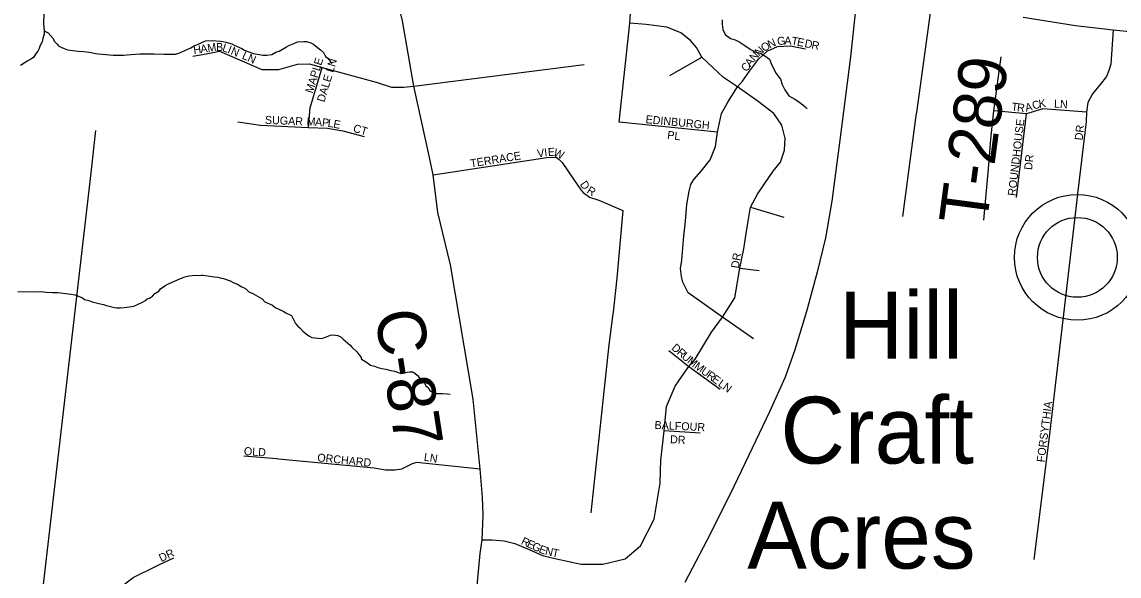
# Model space of a CAD drawing. Extents: x 1310247 to 1664935, y 235267 to 584339.
# Drawn here: x 1455233 to 1462084, y 396572 to 400032 of the extents above; entities that cross this region are included whole.
import ezdxf

# ---------------------------------------------------------------- set-up
doc = ezdxf.new("R2010")
doc.units = 0
for name, color, linetype in [('GM_X_County_Road', 7, 'Continuous'), ('GM_X_County_Road_Text', 7, 'Continuous'), ('GM_X_Interstate_Route', 7, 'Continuous'), ('GM_X_Minor_River', 7, 'Continuous'), ('GM_X_Township_Road', 7, 'Continuous'), ('GM_X_Township_Road_Text', 7, 'Continuous'), ('GM_X_Township_Subdivision', 7, 'Continuous'), ('GM_X_Township_Subdivision_Text', 7, 'Continuous'), ('GM_X_Unincorporated', 7, 'Continuous'), ('GM_X_Unincorporated_Location', 7, 'Continuous'), ('GM_X_Unincorporated_Text', 7, 'Continuous')]:
    doc.layers.add(name, color=color, linetype=linetype)

msp = doc.modelspace()

# ---------------------------------------------------------------- linework, layer by layer
at = {"layer": 'GM_X_County_Road'}
for points in [[(1457856.3, 395425.4), (1457891.7, 395481), (1457954.8, 395574.4), (1457982.6, 395694.4), (1458009.1, 395866), (1458042.1, 396205.5), (1458050.3, 396268.2), (1458060.8, 396355.2), (1458094.8, 396712.8), (1458106.3, 396798.8), (1458113.2, 396952.5), (1458109.1, 397063.7), (1458095.3, 397239.4), (1458051.4, 397675.8), (1457908.7, 398515.8), (1457829.8, 398842.2), (1457800.3, 399077.4), (1457776.8, 399195.4), (1457679.8, 399630.7), (1457608.8, 400039.4), (1457598.6, 400082.1), (1457587, 400144.7), (1457490, 400571.5)], [(1461485.4, 400062.7), (1461812.9, 400010.4), (1462048.4, 399981.8), (1462170.8, 399970.6)]]:
    msp.add_lwpolyline(points, dxfattribs=at)
at = {"layer": 'GM_X_Interstate_Route'}
msp.add_lwpolyline([(1460449.2, 400206.5), (1460406.1, 399814.6), (1460343.4, 399311), (1460290.1, 398913.5), (1460250.5, 398684.1), (1460199.2, 398469.2), (1460133, 398224.6), (1460059, 397984.3), (1459999.2, 397813.7), (1459901.9, 397596.3), (1459772.7, 397325.7), (1459656.5, 397082.8), (1459510.6, 396792.8), (1459371.8, 396532.6)], dxfattribs=at)
at = {"layer": 'GM_X_Minor_River'}
for points in [[(1455219, 400237.4), (1455264.8, 400214.5), (1455296.6, 400197.9), (1455316.6, 400189.5), (1455348.3, 400166.8), (1455356, 400148.6), (1455365.5, 400118.3), (1455369.2, 400094.2), (1455368.6, 400064.1), (1455366.2, 400038), (1455367.9, 400019.9), (1455369.5, 399997.8), (1455371.2, 399977.7), (1455370.9, 399957.6), (1455362.3, 399927.6), (1455358, 399907.6), (1455343.5, 399879.8), (1455339.2, 399865.8), (1455330.9, 399849.9), (1455316.5, 399830.1)], [(1459605.6, 400045.8), (1459604.9, 400017.8), (1459610.1, 399985.5), (1459625.2, 399953), (1459658.6, 399928), (1459686.4, 399919.3), (1459716.1, 399906.5), (1459747.6, 399885.6), (1459781, 399862.6), (1459810.6, 399845.8), (1459844.4, 399836.9), (1459871.9, 399820.1), (1459901.4, 399799.2), (1459910.7, 399772.9), (1459925.9, 399740.4), (1459943.1, 399709.8), (1459970.2, 399675)], [(1455371.2, 399976.7), (1455397.1, 399963.2), (1455426.6, 399928.5), (1455434.3, 399912.3), (1455452.1, 399894), (1455463.9, 399879.7), (1455495.8, 399867.1), (1455517.7, 399858.7), (1455583.8, 399849.5), (1455617.9, 399846.9), (1455635.9, 399844.5), (1455664, 399842), (1455692, 399835.5), (1455710, 399833.2), (1455780.2, 399826), (1455802.2, 399823.6), (1455866.4, 399824.4), (1455888.5, 399826.1), (1455969, 399832.7), (1456021.2, 399833.8), (1456057.3, 399833.1), (1456121.5, 399830), (1456137.5, 399829.7), (1456191.7, 399830.8), (1456211.9, 399836.5), (1456286.7, 399869.3), (1456309, 399882.9), (1456347.5, 399900.3), (1456363.7, 399908.1), (1456379.8, 399913.8), (1456420, 399917.1), (1456472.1, 399912.2), (1456488.1, 399909.9), (1456506.1, 399905.6), (1456544.1, 399894.9), (1456558, 399886.6), (1456605.8, 399865.7), (1456621.7, 399855.4), (1456675.6, 399834.3), (1456701.6, 399829.9), (1456739.6, 399825.2), (1456761.7, 399824.8), (1456793.9, 399828.2), (1456818.2, 399843.9), (1456838.4, 399849.6), (1456885, 399876.8), (1456899.2, 399884.6), (1456929.6, 399898.1), (1456953.8, 399907.8), (1456994, 399909.1), (1457010, 399908.8), (1457036, 399902.3), (1457053.9, 399894), (1457067.7, 399879.7), (1457097.5, 399857), (1457115.3, 399840.7), (1457128.9, 399816.3), (1457142.8, 399806), (1457168.3, 399771.5)], [(1455316.5, 399830.1), (1455304.2, 399810.2), (1455287.9, 399800.5), (1455269.7, 399788.7), (1455223, 399759.4)], [(1459970.2, 399675), (1459981.4, 399640.6), (1459996.5, 399608.1), (1460021.6, 399571.3), (1460059.1, 399550.2), (1460088.6, 399531.4), (1460121.9, 399504.4), (1460137.5, 399490)], [(1456151.6, 398397.9), (1456218.3, 398428.8), (1456250.6, 398440.3), (1456274.8, 398445.9), (1456317, 398451.2), (1456333.1, 398448.9), (1456351.2, 398450.6), (1456365.2, 398450.4), (1456379.2, 398448.1), (1456433.3, 398441.1), (1456455.3, 398438.7), (1456471.3, 398434.4), (1456491.3, 398430.1), (1456533.2, 398415.3), (1456555.1, 398402.8), (1456579, 398394.4), (1456600.9, 398380), (1456628.8, 398367.4), (1456648.5, 398347), (1456674.4, 398336.5), (1456732.1, 398303.4), (1456749.8, 398285), (1456797.7, 398264.1), (1456813.5, 398249.7), (1456863.3, 398226.8), (1456881.2, 398216.4), (1456915, 398197.8), (1456932.5, 398165.3), (1456940.3, 398149.1), (1456956, 398132.8), (1456969.9, 398120.5), (1456987.6, 398100.1), (1457007.4, 398083.7), (1457023.3, 398071.4), (1457043.2, 398061), (1457103.3, 398055.9), (1457117.4, 398059.7), (1457159.8, 398075), (1457175.9, 398078.7), (1457206, 398074.2), (1457225.9, 398063.8), (1457239.7, 398051.5), (1457283.3, 398014.6), (1457295, 397998.3), (1457324.7, 397971.7), (1457336.5, 397955.5), (1457348.3, 397941.2), (1457354, 397927), (1457389.8, 397902.3), (1457409.6, 397887.9), (1457433.6, 397881.5), (1457455.5, 397875.1), (1457479.5, 397868.6), (1457505.5, 397864.1), (1457535.5, 397855.6), (1457559.5, 397851.1), (1457587.5, 397840.6), (1457607.5, 397838.3), (1457637.7, 397845.8), (1457655.8, 397847.5), (1457673.9, 397847.1), (1457687.7, 397836.8), (1457701.6, 397826.6), (1457715.4, 397810.3), (1457737.1, 397789.8), (1457748.9, 397773.5), (1457754.7, 397759.4), (1457768.6, 397749.1), (1457780.3, 397730.8), (1457806.1, 397714.3), (1457822.1, 397712), (1457858.3, 397711.4), (1457888.3, 397708.8), (1457906.4, 397708.5)], [(1455207.3, 398348.2), (1455313.6, 398346.3), (1455351.8, 398347.7), (1455367.8, 398347.4), (1455383.9, 398345.1), (1455424, 398342.4), (1455440, 398342.1), (1455456.1, 398341.8), (1455522.2, 398334.6), (1455540.2, 398332.3), (1455562.2, 398327.9), (1455596.1, 398315.3), (1455610.1, 398309), (1455624, 398298.7), (1455650, 398292.2), (1455671.9, 398283.8), (1455711.9, 398273.1), (1455741.9, 398268.5), (1455759.8, 398262.2), (1455809.8, 398249.3), (1455823.8, 398247), (1455847.9, 398246.6), (1455870, 398248.2), (1455888.1, 398249.9), (1455930.4, 398257.2), (1455985, 398282.3), (1455999.2, 398290.1), (1456015.4, 398301.9), (1456029.6, 398307.7), (1456047.9, 398319.4), (1456062.2, 398335.2), (1456086.5, 398350.8), (1456098.8, 398364.7), (1456131.3, 398388.2), (1456151.6, 398397.9)]]:
    msp.add_lwpolyline(points, dxfattribs=at)
at = {"layer": 'GM_X_Township_Road'}
for points in [[(1460819.9, 399462.9), (1460820.4, 399466.4), (1460915, 400149.1)], [(1460735, 398816.4), (1460819.9, 399462.9)]]:
    msp.add_lwpolyline(points, dxfattribs=at)
at = {"layer": 'GM_X_Township_Subdivision'}
for points in [[(1459575.7, 399343), (1458962.1, 399405.5), (1459029.4, 400024.5), (1459051.7, 400376.9)], [(1459997.9, 399312.6), (1459978.5, 399387.6), (1459928.8, 399460.3), (1459830.6, 399534.2), (1459701.9, 399626), (1459614.8, 399684.2), (1459551.9, 399743.1), (1459477.7, 399811.1), (1459446.3, 399872), (1459408.7, 399915.7), (1459347.7, 399963.4), (1459259.4, 399999), (1459130.3, 400015), (1459029.4, 400024.5)], [(1462048.4, 399981.8), (1462032.4, 399768.9), (1462020.6, 399728.6), (1462006.8, 399691.1), (1461966.6, 399640.6), (1461919.5, 399583.4), (1461889.4, 399528.6), (1461881.9, 399468.7), (1461878.7, 399410.9), (1461825.6, 398959.3), (1461825.3, 398956.8)], [(1459801.7, 398053.1), (1459608.1, 398189.3), (1459392.8, 398340.8), (1459374.4, 398377.6), (1459359.5, 398406.7), (1459352.6, 398441.6), (1459346.2, 398491.3), (1459353.8, 398543.6), (1459366.6, 398694), (1459376.8, 398788.4), (1459385.7, 398892.9), (1459399.7, 398975.8), (1459409.9, 399017.9), (1459427.8, 399048.4), (1459473.7, 399099.5), (1459529.8, 399170.9), (1459564.2, 399255), (1459575.7, 399343), (1459601.2, 399460.3), (1459640.7, 399531.6), (1459701.9, 399626), (1459731.6, 399662.8), (1459776.3, 399724.8), (1459833.1, 399799.9), (1459886, 399848.7), (1459951, 399878.1), (1460032.2, 399882.2), (1460125.6, 399863.9)], [(1456300.4, 399818.5), (1456383.3, 399833.8), (1456466.2, 399849.1), (1456731.4, 399734.5), (1456837.2, 399734.5), (1456954, 399768.3), (1457028.2, 399770.5), (1457106.7, 399746.5), (1457445.5, 399656.5), (1457540.4, 399625.2), (1457616.8, 399624.9), (1457679.4, 399630.7)], [(1459279.8, 399698.5), (1459477.7, 399811.1)], [(1461238.8, 398793.2), (1461270, 399114.8), (1461282.9, 399300.4), (1461301.3, 399476.8), (1461347.2, 399815)], [(1457021.2, 399372.3), (1457032.1, 399495.7), (1457106.7, 399746.5)], [(1457679.4, 399630.7), (1457679.8, 399630.7), (1458744, 399766.4)], [(1461881.9, 399468.7), (1461608.4, 399490.2), (1461507.1, 399458.5), (1461301.3, 399476.8)], [(1456580.9, 399408), (1456722.4, 399387.8), (1457021.2, 399372.3), (1457141.3, 399369.1), (1457237.6, 399351.8), (1457370.7, 399317.1)], [(1461444.6, 398934.7), (1461507.1, 399458.5)], [(1455664.1, 399089.2), (1455694.6, 399353.7)], [(1459220.6, 397231.5), (1459223.1, 397293.5), (1459242.9, 397477.7), (1459258.2, 397630.7), (1459311.7, 397758.2), (1459357.6, 397824.5), (1459397.6, 397880.9), (1459436.7, 397926.5), (1459538.7, 398094.8), (1459608.1, 398189.3), (1459684, 398309), (1459716.2, 398493.6), (1459740.1, 398615), (1459752.9, 398699.1), (1459768.2, 398788.4), (1459783.5, 398875.1), (1459826.8, 398956.6), (1459870.2, 399020.4), (1459923.7, 399100.7), (1459969.6, 399155.6), (1459995.1, 399232), (1459999, 399308.6), (1459997.9, 399312.6)], [(1457800.3, 399077.4), (1458511.6, 399185.2), (1458569.6, 399188.3), (1458588, 399173.4), (1458607.2, 399153.8), (1458676.2, 399050.7), (1458722.1, 398984.6), (1458736.6, 398967.4), (1458776.1, 398938.5), (1458836, 398919.1), (1458985.4, 398853.5), (1458947.4, 398431.4), (1458925.1, 398220.3), (1458923.5, 398208.4)], [(1455235.8, 395385.9), (1455664.1, 399089.2), (1455664.1, 399089.2)], [(1461825.3, 398956.8), (1461644.8, 397421.9), (1461551.1, 396675.7)], [(1459783.5, 398875.1), (1459990, 398813.9)], [(1459716.2, 398493.6), (1459837.6, 398480.8)], [(1458923.5, 398208.4), (1458897.6, 398015.7), (1458785.7, 396966.3)], [(1459273.5, 397980), (1459397.6, 397880.9), (1459593.1, 397738.6)], [(1459467.3, 397465), (1459242.9, 397477.7)], [(1456823.8, 397303), (1456618.6, 397320.5)], [(1458095.3, 397239.4), (1457697.4, 397281.7), (1457669.3, 397273.4), (1457640.7, 397259), (1457602.8, 397239.6), (1457563.8, 397233.5), (1457503.4, 397233.5), (1457431.7, 397244.7), (1456834.7, 397302.1), (1456823.8, 397303)], [(1458106.3, 396798.8), (1458169.5, 396798.8), (1458243.6, 396792), (1458310.8, 396774.1), (1458400, 396737), (1458483.8, 396700), (1458570.2, 396679.4), (1458725.6, 396646.5), (1458859.9, 396646.5), (1458999.9, 396678.7), (1459096.2, 396761.2), (1459181.5, 396926.5), (1459217.4, 397151.6), (1459220.6, 397231.5)], [(1456090.9, 396643.2), (1456181.9, 396686.6)], [(1455695.6, 395280.5), (1455823.1, 396431.8), (1455875.3, 396524.2), (1455926.9, 396561.9), (1456062.5, 396629.6), (1456090.9, 396643.2)]]:
    msp.add_lwpolyline(points, dxfattribs=at)
at = {"layer": 'GM_X_Unincorporated'}
for radius in [392.8, 249]:
    msp.add_circle((1461823.9, 398561.9), radius, dxfattribs=at)
at = {"layer": 'GM_X_Unincorporated_Location'}
msp.add_line((1461823.9, 398561.9), (1461823.9, 398561.9), dxfattribs=at)

# ---------------------------------------------------------------- texts
at = {"layer": 'GM_X_County_Road_Text'}
msp.add_text('C-87', height=300, rotation=278.88173, dxfattribs=at).set_placement((1457435.3, 398216.9))
at = {"layer": 'GM_X_Township_Road_Text'}
msp.add_text('T-289', height=300, rotation=82.466, dxfattribs=at).set_placement((1461256.1, 398754.6))
at = {"layer": 'GM_X_Township_Subdivision_Text'}
for s, rotation, p in [('A', 359.82512, (1459993.7, 399891)), ('H', 8.11464, (1456306.8, 399831.3)), ('A', 8.093, (1456350.4, 399837.5)), ('M', 8.12067, (1456394, 399843.7)), ('B', 358.5673, (1456444.1, 399851)), ('L', 341.94518, (1456479.9, 399850.6)), ('I', 337.85765, (1456512.5, 399840.1)), ('N', 337.8374, (1456532.8, 399831.8)), ('N', 42.20164, (1459836.3, 399814.9)), ('O', 32.74441, (1459867.2, 399843.1)), ('N', 23.34781, (1459902.3, 399865.9)), ('G', 5.97811, (1459951.4, 399886.5)), ('T', 350.44784, (1460035.6, 399891.1)), ('E', 348.33646, (1460069.8, 399885.3)), ('D', 348.22267, (1460117.2, 399875.5)), ('R', 348.23602, (1460160.3, 399866.5)), ('LN', 336.02625, (1456602.8, 399804.2)), ('MAPLE', 72.7179, (1457047.9, 399583)), ('N', 48.41727, (1459808.1, 399783)), ('DALE LN', 73.39085, (1457121.3, 399527.5)), ('C', 53.9994, (1459758.9, 399717)), ('A', 52.57932, (1459782, 399748.8)), ('C', 18.81326, (1461551.2, 399482.9)), ('K', 8.35571, (1461586.3, 399495.1)), ('LN', 356.97755, (1461677.2, 399497.2)), ('T', 352.65811, (1461409.6, 399479.5)), ('R', 352.73134, (1461444.6, 399475)), ('A', 13.6054, (1461503.6, 399471.1)), ('SUGAR', 357.56454, (1456749.1, 399396)), ('M', 356.11809, (1457008.9, 399387.2)), ('A', 356.12776, (1457061.6, 399383.6)), ('P', 355.07524, (1457105.2, 399380.7)), ('L', 351.16659, (1457139.4, 399377.8)), ('E', 349.64384, (1457173.8, 399372.4)), ('EDINBURGH', 354.42825, (1459125.6, 399400.4)), ('ROUNDHOUSE', 83.46221, (1461438.5, 398943.3)), ('CT', 343.60907, (1457296.9, 399347.3)), ('PL', 352.87835, (1459260.5, 399302.7)), ('DR', 83.99458, (1461856.5, 399290.8)), ('TERRACE', 9.16423, (1458036.4, 399123.1)), ('V', 8.31246, (1458454.3, 399184.7)), ('I', 7.05454, (1458497.6, 399191)), ('E', 4.18292, (1458518.8, 399193.7)), ('W', 337.95821, (1458547.9, 399197.2)), ('DR', 83.99458, (1461540.7, 399105.9)), ('D', 305.52752, (1458714.7, 399017.5)), ('R', 327.99316, (1458755.5, 398967.4)), ('DR', 81.03268, (1459709.4, 398490.5)), ('D', 319.62631, (1459284.8, 397990.2)), ('R', 319.60679, (1459318.3, 397961.7)), ('U', 319.61703, (1459348.4, 397936)), ('M', 321.67582, (1459383.5, 397906.3)), ('M', 323.74529, (1459426.4, 397872.3)), ('U', 323.78865, (1459469, 397841.1)), ('R', 323.79781, (1459504.5, 397815.1)), ('E', 323.78582, (1459536.5, 397791.7)), ('L', 323.78582, (1459575.6, 397763.1)), ('N', 323.80443, (1459604, 397742.3)), ('FORSYTHIA', 82.78307, (1461618.9, 397280.2)), ('BALFOUR', 357.35565, (1459182.3, 397490.8)), ('DR', 356.98842, (1459279.1, 397401.5)), ('OLD', 356.04938, (1456617.3, 397328)), ('ORCHARD', 354.14463, (1457075.2, 397288.4)), ('LN', 351.03269, (1457740.1, 397292.7)), ('R', 334.99925, (1458345.5, 396772.7)), ('E', 335.00758, (1458381.4, 396756)), ('DR', 25.20174, (1456102.3, 396658.3)), ('G', 334.99895, (1458413.3, 396741.1)), ('E', 338.08189, (1458455.9, 396721.4)), ('N', 347.15842, (1458496.7, 396705.7)), ('T', 348.2506, (1458540.7, 396695.7))]:
    msp.add_text(s, height=50, rotation=rotation, dxfattribs=at).set_placement(p)
at = {"layer": 'GM_X_Unincorporated_Text'}
for s, p in [('Hill', (1460334.7, 397930)), ('Craft', (1459969.5, 397274.4)), ('Acres', (1459762.7, 396618.8))]:
    msp.add_text(s, height=417, rotation=0.00001, dxfattribs=at).set_placement(p)

doc.saveas('drawing.dxf')
